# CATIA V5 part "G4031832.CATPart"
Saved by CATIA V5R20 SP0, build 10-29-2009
Part number: G4031832
Revision: 5
Definition: design
Nomenclature: G4031832
Source: made
Description: NOT SPECIFIED
Bounding box of the stored display mesh (mm): x -16 to 16, y -15 to 15, z -15 to 15
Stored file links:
  C:\Users\Raffaele\Desktop\3D X SITO CF\BOLEX\27-BUSH REF 403\G4031832.CATPart
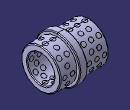
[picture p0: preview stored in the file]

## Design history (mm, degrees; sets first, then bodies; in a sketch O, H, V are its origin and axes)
Body1 "MANIFOLD_SOLID_BREP #9145" (main body)
  Solid1: solid without history
Body2 "MANIFOLD_SOLID_BREP #9288"
  Solid2: solid without history
Body3 "MANIFOLD_SOLID_BREP #9431"
  Solid3: solid without history
Body4 "MANIFOLD_SOLID_BREP #9574"
  Solid4: solid without history
Body5 "MANIFOLD_SOLID_BREP #9717"
  Solid5: solid without history
Body6 "MANIFOLD_SOLID_BREP #9862"
  Solid6: solid without history
Body7 "MANIFOLD_SOLID_BREP #10007"
  Solid7: solid without history
Body8 "MANIFOLD_SOLID_BREP #10152"
  Solid8: solid without history
Body9 "MANIFOLD_SOLID_BREP #10297"
  Solid9: solid without history
Body10 "MANIFOLD_SOLID_BREP #10442"
  Solid10: solid without history
Body11 "MANIFOLD_SOLID_BREP #10587"
  Solid11: solid without history
Body12 "MANIFOLD_SOLID_BREP #10732"
  Solid12: solid without history
Body13 "MANIFOLD_SOLID_BREP #10877"
  Solid13: solid without history
Body14 "MANIFOLD_SOLID_BREP #11022"
  Solid14: solid without history
Body15 "MANIFOLD_SOLID_BREP #11167"
  Solid15: solid without history
Body16 "MANIFOLD_SOLID_BREP #11312"
  Solid16: solid without history
Body17 "MANIFOLD_SOLID_BREP #11457"
  Solid17: solid without history
Body18 "MANIFOLD_SOLID_BREP #11602"
  Solid18: solid without history
Body19 "MANIFOLD_SOLID_BREP #11747"
  Solid19: solid without history
Body20 "MANIFOLD_SOLID_BREP #11894"
  Solid20: solid without history
Body21 "MANIFOLD_SOLID_BREP #12041"
  Solid21: solid without history
Body22 "MANIFOLD_SOLID_BREP #12186"
  Solid22: solid without history
Body23 "MANIFOLD_SOLID_BREP #12333"
  Solid23: solid without history
Body24 "MANIFOLD_SOLID_BREP #12480"
  Solid24: solid without history
Body25 "MANIFOLD_SOLID_BREP #12625"
  Solid25: solid without history
Body26 "MANIFOLD_SOLID_BREP #12770"
  Solid26: solid without history
Body27 "MANIFOLD_SOLID_BREP #12915"
  Solid27: solid without history
Body28 "MANIFOLD_SOLID_BREP #13060"
  Solid28: solid without history
Body29 "MANIFOLD_SOLID_BREP #13205"
  Solid29: solid without history
Body30 "MANIFOLD_SOLID_BREP #13350"
  Solid30: solid without history
Body31 "MANIFOLD_SOLID_BREP #13495"
  Solid31: solid without history
Body32 "MANIFOLD_SOLID_BREP #13638"
  Solid32: solid without history
Body33 "MANIFOLD_SOLID_BREP #13781"
  Solid33: solid without history
Body34 "MANIFOLD_SOLID_BREP #13926"
  Solid34: solid without history
Body35 "MANIFOLD_SOLID_BREP #14071"
  Solid35: solid without history
Body36 "MANIFOLD_SOLID_BREP #14216"
  Solid36: solid without history
Body37 "MANIFOLD_SOLID_BREP #14361"
  Solid37: solid without history
Body38 "MANIFOLD_SOLID_BREP #14506"
  Solid38: solid without history
Body39 "MANIFOLD_SOLID_BREP #14651"
  Solid39: solid without history
Body40 "MANIFOLD_SOLID_BREP #14796"
  Solid40: solid without history
Body41 "MANIFOLD_SOLID_BREP #14941"
  Solid41: solid without history
Body42 "MANIFOLD_SOLID_BREP #15086"
  Solid42: solid without history
Body43 "MANIFOLD_SOLID_BREP #15231"
  Solid43: solid without history
Body44 "MANIFOLD_SOLID_BREP #15376"
  Solid44: solid without history
Body45 "MANIFOLD_SOLID_BREP #15521"
  Solid45: solid without history
Body46 "MANIFOLD_SOLID_BREP #15666"
  Solid46: solid without history
Body47 "MANIFOLD_SOLID_BREP #15811"
  Solid47: solid without history
Body48 "MANIFOLD_SOLID_BREP #15958"
  Solid48: solid without history
Body49 "MANIFOLD_SOLID_BREP #16105"
  Solid49: solid without history
Body50 "MANIFOLD_SOLID_BREP #16250"
  Solid50: solid without history
Body51 "MANIFOLD_SOLID_BREP #16397"
  Solid51: solid without history
Body52 "MANIFOLD_SOLID_BREP #16544"
  Solid52: solid without history
Body53 "MANIFOLD_SOLID_BREP #16689"
  Solid53: solid without history
Body54 "MANIFOLD_SOLID_BREP #16832"
  Solid54: solid without history
Body55 "MANIFOLD_SOLID_BREP #16975"
  Solid55: solid without history
Body56 "MANIFOLD_SOLID_BREP #17118"
  Solid56: solid without history
Body57 "MANIFOLD_SOLID_BREP #17261"
  Solid57: solid without history
Body58 "MANIFOLD_SOLID_BREP #17406"
  Solid58: solid without history
Body59 "MANIFOLD_SOLID_BREP #17551"
  Solid59: solid without history
Body60 "MANIFOLD_SOLID_BREP #17698"
  Solid60: solid without history
Body61 "MANIFOLD_SOLID_BREP #17845"
  Solid61: solid without history
Body62 "MANIFOLD_SOLID_BREP #17990"
  Solid62: solid without history
Body63 "MANIFOLD_SOLID_BREP #18137"
  Solid63: solid without history
Body64 "MANIFOLD_SOLID_BREP #18284"
  Solid64: solid without history
Body65 "MANIFOLD_SOLID_BREP #18429"
  Solid65: solid without history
